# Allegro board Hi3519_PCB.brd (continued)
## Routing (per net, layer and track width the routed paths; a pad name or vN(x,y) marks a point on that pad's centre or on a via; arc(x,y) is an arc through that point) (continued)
SDIO1_CDATA1: length 66.9
  TOP w0.127: J12.8 R156.2 147.4,25.47 147.21,25.27 145.59,25.27 145.32,25.54 v2(144.05,25.54) ; v2(102.52,52.68) 102.18,52.34 R882.2
  ART03 w0.127: v2(144.05,25.54) 144.14,25.63 144.14,36.89 139.93,41.1 132.96,41.1 121.15,52.91 115.31,52.91 115,52.59 102.61,52.59 v2(102.52,52.68)
SDIO1_CDATA2: length 66.9
  TOP w0.127: J12.1 R157.2 147.4,33.75 147.1,34.05 144.73,34.05 143.21,35.57 v2(143.03,35.57) ; R880.2 v2(100.23,50.81)
  ART03 w0.127: v2(100.23,50.81) 100.23,50.33 100.44,50.13 101.68,50.13 101.9,50.35 101.9,51.43 102.3,51.83 114.97,51.83 115.22,51.58 120.49,51.58 131.85,40.21 134.34,40.21 134.49,40.06 134.49,39.7 134.64,39.55 134.85,39.55 135,39.7 135,40.19 135.15,40.34 135.36,40.34 135.51,40.19 135.51,39.7 135.66,39.55 135.87,39.55 136.02,39.7 136.02,40.19 136.17,40.34 136.38,40.34 136.53,40.19 136.53,39.7 136.67,39.55 136.88,39.55 137.03,39.7 137.03,40.19 137.18,40.34 137.39,40.34 137.54,40.19 137.54,39.7 137.69,39.55 137.9,39.55 138.05,39.7 138.05,40.19 138.2,40.34 138.41,40.34 138.56,40.19 138.56,39.7 138.71,39.55 138.93,39.55 139.08,39.7 139.08,40.19 139.23,40.34 139.44,40.34 139.59,40.19 139.59,39.7 139.74,39.55 140.4,39.55 143.03,36.92 v2(143.03,35.57)
SDIO1_CDATA3: length 64.4
  TOP w0.127: R788.2 v2(100.23,51.83) ; v2(143.67,34.1) 144.86,32.91 147.22,32.91 147.4,32.73 R154.2 J12.2
  ART03 w0.127: v2(143.67,34.1) 143.67,36.82 139.77,40.72 132.81,40.72 120.99,52.53 115.54,52.53 115.22,52.21 101.63,52.21 101.38,51.96 101.38,50.69 101.25,50.56 101,50.56 100.87,50.69 100.87,52.47 100.74,52.59 100.36,52.59 100.23,52.47 v2(100.23,51.83)
SDIO1_VOUT: length 80.7
  TOP w0.254: U3.M19 v1(93.7,50.79)
  TOP w0.381: R157.1 v2(145.93,33.48) ; R156.1 v2(145.9,25.78) ; v2(145.93,31.28) R153.1 R154.1 ; R155.1 v2(145.9,26.88)
  ART03 w0.381: v2(145.9,25.78) v2(145.9,26.88) 145.9,27.17 146.56,27.83 146.56,30.65 v2(145.93,31.28) 146.08,31.43 146.08,33.33 v2(145.93,33.48) 146.59,34.14 146.59,37.99 141.38,43.19 140.11,43.19 139.48,43.83 133.89,43.83 122.42,55.3 98.7,55.3 97.44,54.04 97.44,51.83 96.91,51.3 94.06,51.3 93.7,50.94 v1(93.7,50.79)
SELRGV: length 4.4
  TOP w0.127: R148.2 118.5,75.58 118.67,75.4 R1000.2 119,75.07 119.16,75.23 119.67,75.23 119.72,75.17 U2.14
SENSOR_CLK: length 39
  TOP w0.127: v2(53.75,39.64) 54.42,40.31 56.3,40.31 56.41,40.2 J1.12
  BOTTOM w0.127: v2(53.75,39.64) 53.75,37.45 56.01,35.19 71.66,35.19 77.24,40.78 81.92,40.78 82.83,41.7 R22.1
SENSOR_HS: length 42.8
  TOP w0.127: J1.18 54.15,41.4 v2(53.75,41.8)
  BOTTOM w0.127: v2(53.75,41.8) 53.24,41.29 53.24,37.42 55.85,34.81 71.81,34.81 77.4,40.4 82.1,40.4 R23.1
SENSOR_RSTN: length 42.3
  TOP w0.127: v1(83.3,44.94) 83.62,45.26 U3.Y4 ; J1.14 56.55,40.6 56.36,40.78 v2(53.75,40.78)
  BOTTOM w0.127: v1(83.3,44.94) 82.91,44.55 82.91,44.06 82.25,43.4 82.25,41.7 81.72,41.16 77.09,41.16 71.5,35.57 56.16,35.57 54.26,37.48 54.26,40.27 v2(53.75,40.78)
SENSOR_VS: length 37.7
  TOP w0.127: v2(54.89,42.43) 55.53,41.8 J1.20
  BOTTOM w0.127: v2(54.89,42.43) 54.74,42.28 54.74,37.54 56.32,35.96 71.34,35.96 76.93,41.54 81.44,41.54 81.69,41.8 R24.1
SGM8903_OUTL: length 5.8
  TOP w0.203: J30.1 9.58,32.17 10.03,32.62 D12.1 C215.1 R133.2
SGM8903_OUTR: length 9.6
  TOP w0.203: R134.1 C214.1 D11.1 6.87,29.62 6.43,30.06 J30.3
SHUTTER_TRIG: length 40.8
  TOP w0.127: U3.W14 v1(89.8,46.24) ; v2(123.73,38.75) 123.73,38.88 123.21,39.4 J18.60
  ART03 w0.127: v1(89.8,46.24) 89.8,47.11 90.07,47.39 91.85,47.39 92.36,46.88 92.36,46.24 92.86,45.73 98.86,45.73 99.79,44.81 101.37,44.81 102.25,43.92 116.61,43.92 121.27,39.26 123.22,39.26 v2(123.73,38.75)
SHUTTER_TRIG_C: length 55.7
  TOP w0.127: J17.5 J17.6 11.33,76.34 12.86,77.87 33.56,77.87 34.83,76.6 34.83,70.25 35.46,69.61 35.46,67.32 37.37,65.42 v2(37.37,64.91)
  BOTTOM w0.127: J19.60 41.18,54.6 37.67,58.1 37.67,63.46 37.37,63.77 v2(37.37,64.91)
SPI0_CSN: length 34.2
  TOP w0.127: J1.2 56.75,38.2 56.47,37.91 v2(56.47,37.18) ; v2(75.7,42.69) 82.35,42.69 U3.AB4
  BOTTOM w0.127: R135.1 v2(75.7,42.69) 75.34,42.33 75.34,41.04 71.02,36.72 56.93,36.72 v2(56.47,37.18)
SPI0_MISO: length 33.1
  TOP w0.127: v2(74.91,43.19) 82.2,43.19 U3.AB3 ; J1.4 56.67,38.6 55.93,37.86 v2(55.81,37.86)
  BOTTOM w0.127: v2(74.91,43.19) 74.91,41.14 70.87,37.1 57.69,37.1 56.93,37.86 v2(55.81,37.86)
SPI0_MOSI/I2C0_SDA: length 33.4
  TOP w0.127: v2(75.7,43.7) 80.8,43.7 80.93,43.58 81.94,43.58 U3.AB2 ; v2(56.17,38.75) 56.42,39 J1.6
  BOTTOM w0.127: v2(56.17,38.75) 56.67,38.75 57.94,37.48 70.71,37.48 74.44,41.21 74.44,43.51 74.63,43.7 v2(75.7,43.7) R51.1
SPI0_SCLK/I2C0_SCL: length 31.7
  TOP w0.127: v2(55.28,39.08) 55.52,39.33 56.34,39.33 56.41,39.4 J1.8
  BOTTOM w0.127: R500.1 R43.1 79.43,41.92 76.77,41.92 71.18,36.34 56.48,36.34 55.28,37.54 v2(55.28,39.08)
SVB_PWM_CPU: length 21.9
  TOP w0.127: U3.W16 91.1,45.59 v1(91.1,45.59)
  BOTTOM w0.127: v1(91.1,45.59) 91.1,44.33 91.52,43.91 93.12,43.91 93.38,44.16 98,44.16 98.71,43.45 101.76,43.45 102.68,42.52 109.34,42.52 109.63,42.81 R200.1
SVB_PWM_DDR: length 12
  TOP w0.127: v1(92.4,44.29) 92.4,44.94 U3.Y17
  BOTTOM w0.127: v1(92.4,44.29) 92.65,44.54 102.32,44.54 R202.2
SVB_PWM_MEDIA: length 28.5
  TOP w0.127: U3.Y16 91.1,44.94 91.1,38.2 v2(92.72,36.59)
  ART03 w0.127: v2(92.72,36.59) 93.58,35.73 107.32,35.73 108.82,34.23 v2(108.82,33.37)
  BOTTOM w0.127: R192.1 v2(108.82,33.37)
SVB_PWM_VDD: length 20.7
  TOP w0.127: U3.Y15 v1(90.45,45.59)
  ART03 w0.127: v2(91.34,28.72) 91.03,29.03 91.03,38.62 92.28,39.88 v1(92.28,40.68)
  BOTTOM w0.127: v1(90.45,45.59) 90.45,44.34 91.85,42.94 91.85,41.11 v1(92.28,40.68) ; R207.1 v2(91.34,28.72)
SYS_RSTN_OUT: length 45.5
  TOP w0.127: v2(76.87,30.24) 76.46,30.65 U16.3 ; v1(83.95,49.49) U3.P4 ; v2(88.73,30.62) U13.2
  ART03 w0.127: v2(76.87,30.24) 77.45,30.83 84.03,30.83 84.87,29.99 88.09,29.99 v2(88.73,30.62)
  ART04 w0.127: v1(83.95,49.49) 83.57,49.11 81.91,49.11 81.31,48.5 79.25,48.5 78.83,48.08 78.83,47.31 77.69,46.17 77.69,41 77.15,40.47 77.15,30.53 v2(76.87,30.24)
  BOTTOM w0.127: R213.2 77.75,28.97 76.87,29.86 v2(76.87,30.24) C212.2
TEST_MODE: length 3.9
  TOP w0.127: U3.R2 82,48.19 81.18,48.19 80.71,47.72 80.12,47.72 79.41,47.01 R93.1
TX0+_SII9022A: length 14.6
  TOP w0.102: J28.7 151.97,51.68 151.61,51.32 151.27,51.32 150.64,50.69 149.44,50.69 149.33,50.8 U12.10 U12.1 147.15,50.8 147.04,50.69 140.81,50.69 140.7,50.8 U22.62
TX0-_SII9022A: length 14.6
  TOP w0.102: J28.9 151.97,50.68 151.61,51.04 151.39,51.04 150.75,50.41 149.44,50.41 149.33,50.3 U12.9 U12.2 147.15,50.3 147.04,50.41 140.81,50.41 140.7,50.3 U22.61
TX1+_SII9022A: length 14.6
  TOP w0.102: J28.4 151.84,53.18 151.48,52.82 151.12,52.82 150.66,52.36 149.44,52.36 149.33,52.47 U11.7 U11.4 147.15,52.47 147.04,52.36 146.1,52.36 145.93,52.19 140.81,52.19 140.7,52.3 U22.65
TX1-_SII9022A: length 14.6
  TOP w0.102: U22.64 140.7,51.8 140.81,51.91 146.05,51.91 146.22,52.08 147.04,52.08 147.15,51.97 U11.5 U11.6 149.33,51.97 149.44,52.08 150.78,52.08 151.23,52.54 151.48,52.54 151.84,52.18 J28.6
TX2+_SII9022A: length 14.6
  TOP w0.102: U22.68 140.7,53.8 140.81,53.69 145.12,53.69 145.29,53.86 147.06,53.86 147.18,53.97 U11.1 U11.10 149.33,53.97 149.44,53.86 150.44,53.86 150.89,54.32 151.48,54.32 151.84,54.68 J28.1
TX2-_SII9022A: length 14.6
  TOP w0.102: J28.3 151.84,53.68 151.48,54.04 151.01,54.04 150.55,53.58 149.44,53.58 149.33,53.47 U11.9 U11.2 147.18,53.47 147.06,53.58 145.41,53.58 145.24,53.41 140.81,53.41 140.7,53.3 U22.67
TX_DSCL_SII9022A: length 20.1
  TOP w0.127: v2(137.45,45.48) 136.72,46.21 U22.49 ; v2(145.83,46.05) U17.1 147.28,46.05 147.99,46.75 150.49,46.75 151.41,47.68 J28.15
  ART03 w0.127: v2(145.83,46.05) 145.63,46.24 138.21,46.24 v2(137.45,45.48)
  BOTTOM w0.127: R183.1 v2(145.83,46.05)
TX_DSDA_SII9022A: length 20.9
  TOP w0.127: v2(148.05,46.05) U17.6 150.46,46.05 151.59,47.18 J28.16 ; U22.48 136.22,45.85 v2(136.59,45.48)
  ART03 w0.127: v2(148.05,46.05) 147.48,46.62 137.73,46.62 v2(136.59,45.48)
  BOTTOM w0.127: R184.1 v2(148.05,46.05)
TXC+_SII9022A: length 14.6
  TOP w0.102: U22.59 140.45,49.3 140.56,49.19 147.04,49.19 147.15,49.3 U12.4 U12.7 149.33,49.3 149.44,49.19 150.54,49.19 151.17,49.82 151.61,49.82 151.97,50.18 J28.10
TXC-_SII9022A: length 14.6
  TOP w0.102: J28.12 152.46,49.18 152.45,49.19 151.96,49.19 151.61,49.54 151.28,49.54 150.65,48.91 149.44,48.91 149.33,48.8 U12.6 U12.5 147.15,48.8 147.04,48.91 140.56,48.91 140.45,48.8 U22.58
TXDLY: length 6.6
  TOP w0.127: U2.16 119.7,74.37 119.65,74.31 119.27,74.31 119.23,74.35 117.1,74.35 116.89,74.56 R146.2 116.39,74.92 116.24,75.07 R1001.2
UART0_RXD: length 38.9
  TOP w0.127: U3.Y19 v1(93.7,44.94)
  ART03 w0.127: v1(93.7,44.94) 93.22,44.46 93.22,39.74 91.79,38.31 91.79,30.05 96.12,25.72 96.12,9.68 J25.3
UART0_TXD: length 38.8
  TOP w0.127: U3.Y18 v1(93.05,44.94)
  ART03 w0.127: J25.2 95.74,9.76 95.74,25.56 91.41,29.89 91.41,38.47 92.84,39.9 92.84,44.73 v1(93.05,44.94)
UART1_RTSN: length 33.9
  TOP w0.127: J18.58 123.3,40.2 v2(123.73,39.77) ; U3.V20 94.03,46.56 v1(94.35,46.24)
  ART03 w0.127: v2(123.73,39.77) 121.3,39.77 116.77,44.3 102.41,44.3 100.9,45.81 99.33,45.81 98.9,46.24 v1(94.35,46.24)
UART1_RTSN_C: length 21.7
  TOP w0.381: R230.1 R231.1 42.7,67.32 38.13,62.75 v2(36.99,62.75)
  BOTTOM w0.381: v2(36.99,62.75) 37.17,62.58 37.17,57.88 41.25,53.8 J19.58
UART1_RXD: length 35.6
  TOP w0.127: U3.U20 v1(94.35,46.89) ; J18.52 123.31,42.6 123.73,42.18 v2(123.73,40.78)
  ART03 w0.127: v2(123.73,40.78) 121.77,40.78 117.87,44.68 102.57,44.68 101.06,46.19 99.48,46.19 98.23,47.44 94.9,47.44 v1(94.35,46.89)
UART1_RXD_C: length 21.4
  TOP w0.127: v2(37.24,66.94) U6.1
  BOTTOM w0.127: v2(37.24,66.94) 35.49,65.19 35.49,56.24 36.98,54.75 38.01,54.75 41.36,51.4 J19.52
UART1_TXD: length 32.2
  TOP w0.127: J18.54 v2(121.44,41.8) ; U3.V19 v1(93.7,46.89)
  ART03 w0.127: v2(121.44,41.8) 118.18,45.06 102.73,45.06 101.22,46.57 99.64,46.57 98.39,47.82 94.63,47.82 v1(93.7,46.89)
UART1_TXD_C: length 23.5
  TOP w0.127: U6.4 41.05,67.58 40.04,66.56 v2(39.91,66.56)
  BOTTOM w0.127: J19.54 41.1,52.2 38.17,55.13 37.14,55.13 35.87,56.4 35.87,64.81 37.62,66.56 v2(39.91,66.56)
USB2_DM: length 30.5
  TOP w0.135: J18.17 117.37,56.2 117.13,55.95 116.92,55.95 115.47,57.4 115.47,59.5 114.61,60.37 105.67,60.37 104.83,59.53 104.83,57.4 102.38,54.96 100.59,54.96 100.44,55.11 100.44,55.36 100.29,55.51 100.08,55.51 99.93,55.36 99.93,55.11 99.77,54.96 97.94,54.96 97.34,54.35 95.34,54.35 U3.F22
USB2_DM_C: length 48.7
  TOP w0.135: v2(9.19,34.85) 9.46,35.13 9.46,35.23 D4.1 9.48,35.93 9.48,39.3 J14.2
  ART04 w0.114: v2(46.83,37.72) 46.62,37.93 45.82,37.93 45.52,37.63 45.52,34.95 44.49,33.92 9.68,33.92 9.35,34.25 9.35,34.69 v2(9.19,34.85)
  BOTTOM w0.135: J19.17 46.76,37.8 v2(46.83,37.72)
USB2_DP: length 30.5
  TOP w0.135: J18.19 117.37,55.4 117.13,55.64 116.79,55.64 115.16,57.27 115.16,59.37 114.48,60.05 105.8,60.05 105.14,59.4 105.14,57.27 102.51,54.64 98.07,54.64 97.47,54.04 95,54.04 U3.F21
USB2_DP_C: length 48.7
  TOP w0.135: v2(10.05,34.85) 9.78,35.13 9.78,35.23 D3.1 9.79,35.9 9.79,39.3 J14.3
  ART04 w0.114: v2(46.83,38.6) 46.83,38.33 46.71,38.21 45.71,38.21 45.24,37.75 45.24,35.07 44.38,34.2 9.8,34.2 9.63,34.37 9.63,34.67 9.81,34.85 v2(10.05,34.85)
  BOTTOM w0.135: J19.19 v2(46.83,38.6)
USB2_OVRCUR: length 42.5
  TOP w0.127: v1(91.75,44.94) 91.43,44.61 U3.AA16 ; v2(101.12,57.55) 101.12,60.09 102.42,61.38 114.84,61.38 117.62,58.6 J18.11
  BOTTOM w0.127: v2(101.12,57.55) 101.25,57.42 101.25,47.23 99.5,45.48 92.99,45.48 92.74,45.23 92.04,45.23 v1(91.75,44.94)
USB2_OVRCUR_C: length 32.9
  TOP w0.127: U1.3 23.27,46.23 23.14,46.1 23.14,44.21 v2(23.4,43.96)
  ART03 w0.127: v2(46.89,35.4) 46.31,34.81 42.45,34.81 34.96,42.31 30.26,42.31 28.61,43.96 v2(23.4,43.96)
  BOTTOM w0.127: J19.11 v2(46.89,35.4) ; v2(23.4,43.96) 22.89,44.46 R69.2
USB2_PWREN: length 30.3
  TOP w0.127: U3.F19 93.44,54.36 93.76,54.68 95.52,54.68 95.58,54.62 96.3,54.62 97.44,55.77 98.71,55.77 100.36,57.42 100.36,59.86 102.26,61.76 115,61.76 117.36,59.4 J18.9
USB2_PWREN_C: length 31.4
  TOP w0.127: v2(24.39,42.99) 25.46,44.06 R152.1 25.47,45.24 U1.4
  ART03 w0.127: v2(46.87,34.38) 46.82,34.43 42.29,34.43 34.8,41.92 30.1,41.92 28.45,43.58 24.97,43.58 v2(24.39,42.99)
  BOTTOM w0.127: v2(46.87,34.38) 46.65,34.6 J19.9
VDAC_CVBS: length 52.2
  TOP w0.127: J18.66 123.65,37 124.31,36.34 124.31,29.17 122.92,27.78 117.18,27.78 109.23,35.73 95.23,35.73 94.62,36.34 94.62,38.6 93.71,39.51 93.71,42.99 v1(93.91,43.19) 94.02,43.31 U3.AB20
  BOTTOM w0.127: R129.2 94.04,43.07 v1(93.91,43.19)
VDAC_CVBS_C: length 33.9
  TOP w0.127: v2(14,54.62) D2.1 J15.1
  ART04 w0.127: v2(40.93,56.78) 37.62,56.78 34.7,53.86 14.76,53.86 v2(14,54.62)
  BOTTOM w0.127: v2(40.93,56.78) 41.14,57 J19.66
VO_CLK: length 73.2
  TOP w0.127: U22.22 128.57,54.3 128.17,54.7 128.17,58.56 125.76,60.98 125.76,62.88 121.75,66.89 118.02,66.89 116.72,65.59 116.72,62.45 116.57,62.3 116.36,62.3 116.21,62.44 116.21,63.85 116.09,63.97 115.85,63.97 115.71,63.82 115.71,62.4 115.58,62.27 115.35,62.27 115.2,62.42 115.2,63.29 115.07,63.41 114.81,63.41 114.69,63.29 114.69,62.42 114.54,62.27 114.33,62.27 114.18,62.42 114.18,63.29 114.06,63.41 113.8,63.41 113.67,63.29 113.67,62.42 113.52,62.27 113.31,62.27 113.17,62.42 113.17,63.29 113.04,63.41 112.78,63.41 112.66,63.29 112.66,62.42 112.51,62.27 112.3,62.27 112.15,62.42 112.15,63.29 112.03,63.41 111.77,63.41 111.64,63.29 111.64,62.42 111.49,62.27 111.28,62.27 111.13,62.42 111.13,63.29 111.01,63.41 110.75,63.41 110.63,63.29 110.63,62.42 110.48,62.27 110.27,62.27 110.12,62.42 110.12,63.29 109.99,63.41 109.73,63.41 109.61,63.29 109.61,62.42 109.46,62.27 109.25,62.27 109.1,62.42 109.1,63.29 108.98,63.41 108.72,63.41 108.59,63.29 108.59,62.42 108.44,62.27 108.23,62.27 108.09,62.42 108.09,63.29 107.96,63.41 107.7,63.41 107.58,63.29 107.58,62.42 107.43,62.27 107.22,62.27 107.07,62.42 107.07,63.29 106.95,63.41 106.69,63.41 106.56,63.29 106.56,62.42 106.41,62.27 106.2,62.27 106.05,62.42 106.05,63.29 105.93,63.41 105.67,63.41 105.55,63.29 105.55,62.42 105.4,62.27 105.19,62.27 105.04,62.42 105.04,63.29 104.91,63.41 104.65,63.41 104.53,63.29 104.53,62.42 104.38,62.27 104.17,62.27 104.02,62.42 104.02,63.29 103.9,63.41 103.64,63.41 103.51,63.29 103.51,62.42 103.36,62.27 103.15,62.27 103.01,62.42 103.01,63.29 102.88,63.41 102.63,63.41 102.5,63.28 102.5,62.42 102.35,62.27 102.04,62.27 99.22,59.45 R700.1
VO_DATA0/BOOT_SEL0: length 80.5
  TOP w0.127: v2(99.85,58.05) 99.85,57.61 98.39,56.15 97.39,56.15 96.63,55.39 95.88,55.39 95.51,55.01 U3.E22 ; U22.13 v2(133.22,59.2) ; SW1.4 v2(98.81,76.46)
  ART03 w0.127: v2(99.85,58.05) 99.85,58.94 95.66,63.13 95.66,70.75 98.2,73.29 98.2,75.85 v2(98.81,76.46) 103.35,81 110.84,81 116.39,75.46 117.44,75.46 117.76,75.14 117.76,72.66 120.95,69.47 120.95,68.96 122.59,67.32 124.04,67.32 126.46,64.91 127.32,64.91 130.24,61.99 131.86,61.99 132.87,60.97 132.87,59.54 v2(133.22,59.2)
  BOTTOM w0.127: R60.2 v2(98.81,76.46)
VO_DATA1/BOOT_SEL1: length 82.4
  TOP w0.127: SW1.3 v2(97.56,76.46) ; U22.11 134.22,57.09 133.89,57.42 133.89,59.7 v2(133.38,60.21) ; U3.E21 95,55.34 95.5,55.34 95.78,55.63 96.46,55.63 97.36,56.53 98.23,56.53 98.96,57.26 v2(98.96,58.56)
  ART03 w0.127: v2(133.38,60.21) 133.38,61.01 132.01,62.37 130.4,62.37 127.48,65.29 126.62,65.29 123.44,68.47 121.98,68.47 121.33,69.12 121.33,69.72 118.14,72.91 118.14,75.29 117.59,75.84 116.55,75.84 111,81.38 102.48,81.38 v2(97.56,76.46) 96.93,75.83 96.93,72.91 95.28,71.26 95.28,61.86 98.58,58.56 v2(98.96,58.56)
  BOTTOM w0.127: R61.2 v2(97.56,76.46)
VO_DATA2/BOOTROM_SEL: length 87
  TOP w0.127: SW2.4 v2(91.82,76.46) ; v2(134.9,60.97) 134.27,60.34 134.27,57.8 134.72,57.35 U22.10 ; v2(97.57,57.04) 97.49,57.04 96.32,55.87 95.68,55.87 95.48,55.66 U3.D22
  ART03 w0.127: v2(134.9,60.97) 134.9,61.12 127.68,68.34 125.89,68.34 123.88,70.35 123.88,71.17 112.52,82.53 97.89,82.53 v2(91.82,76.46) 91.82,75.72 94.14,73.4 94.14,60.47 v2(97.57,57.04)
  BOTTOM w0.127: R67.2 v2(91.82,76.46)
VO_DATA3/SFC_EMMC_BOOT_MODE: length 84.9
  TOP w0.127: v2(135.41,60.09) 135.16,60.09 134.65,59.58 134.65,58.18 135.22,57.61 U22.9 ; U3.D21 95.01,56 95.47,56 95.58,56.11 96.18,56.11 97.06,56.99 97.06,57.29 97.69,57.93 v2(98.07,57.93) ; SW1.1 v2(95.06,76.46)
  ART03 w0.127: v2(98.07,57.93) 97.44,57.93 94.52,60.85 94.52,75.92 v2(95.06,76.46) 100.74,82.15 112.37,82.15 118.92,75.59 118.92,74.07 125.92,67.07 128.41,67.07 134.27,61.21 134.27,60.59 134.78,60.09 v2(135.41,60.09)
  BOTTOM w0.127: R63.2 v2(95.06,76.46)
VO_DATA4/SFC_DEVICE_MODE: length 80.1
  TOP w0.127: v2(135.16,59.07) 135.72,58.51 U22.8 ; U3.C22 95.36,56.35 96.02,56.35 96.68,57.01 96.68,57.93 v2(97.57,58.82) ; SW1.2 v2(96.31,76.46)
  ART03 w0.127: v2(97.57,58.82) 97.44,58.82 94.9,61.36 94.9,71.52 95.72,72.34 95.72,75.88 v2(96.31,76.46) 101.61,81.76 111.16,81.76 116.7,76.22 117.75,76.22 118.54,75.43 118.54,73.91 118.67,73.78 126.77,65.67 127.64,65.67 130.56,62.75 132.19,62.75 133.89,61.06 133.89,60.34 v2(135.16,59.07)
  BOTTOM w0.127: R62.2 v2(96.31,76.46)
VO_DATA5: length 73.6
  TOP w0.127: v1(96.3,57.16) 95.78,56.64 95,56.64 U3.C21 ; U22.7 v2(136.22,59.07)
  ART03 w0.127: v2(136.22,59.07) 134.91,57.76 130.81,57.76 130.43,57.38 108.88,57.38 108.63,57.63 108.63,60.65 108.48,60.8 108.27,60.8 108.13,60.65 108.13,57.53 107.98,57.38 107.77,57.38 107.62,57.53 107.62,60.65 107.47,60.8 107.26,60.8 107.11,60.65 107.11,57.77 106.82,57.48 105.43,57.48 105.08,57.83 105.08,65.01 104.81,65.29 101,65.29 100.51,64.81 100.51,57.24 99.8,56.53 96.93,56.53 v1(96.3,57.16)
VO_DATA6/UPDATE_FROM_SDIO0: length 86.7
  TOP w0.127: SW2.3 v2(90.57,76.46) ; U3.D20 v1(94.35,55.99) ; v2(136.68,60.09) 136.72,60.05 U22.6
  ART03 w0.127: v1(94.35,55.99) 94.3,55.99 93.76,56.53 93.76,73.02 90.57,76.21 v2(90.57,76.46) 97.02,82.91 112.68,82.91 126.87,68.72 127.84,68.72 136.48,60.09 v2(136.68,60.09)
  BOTTOM w0.127: R66.2 v2(90.57,76.46)
VO_DATA7: length 73.3
  TOP w0.127: U3.C20 v1(94.35,56.64) ; U22.4 137.72,57.12 137.29,57.55 v2(137.29,59.07)
  ART03 w0.127: v2(137.29,59.07) 135.6,57.38 130.97,57.38 129.96,56.37 118.95,56.37 118.81,56.5 118.81,56.85 118.66,57 118.45,57 118.3,56.85 118.3,56.04 118.15,55.89 117.94,55.89 117.8,56.04 117.8,56.85 117.65,57 117.44,57 117.29,56.85 117.29,56.04 117.14,55.89 116.93,55.89 116.78,56.04 116.78,56.85 116.63,57 116.42,57 116.27,56.85 116.27,56.04 116.12,55.89 115.91,55.89 115.76,56.04 115.76,56.85 115.61,57 115.4,57 115.26,56.85 115.26,56.04 115.11,55.89 114.9,55.89 114.75,56.04 114.75,56.85 114.6,57 114.39,57 114.24,56.85 114.24,56.04 114.09,55.89 113.88,55.89 113.73,56.04 113.73,56.85 113.58,57 113.37,57 113.22,56.85 113.22,56.04 113.07,55.89 112.86,55.89 112.72,56.04 112.72,56.85 112.57,57 112.36,57 112.21,56.85 112.21,56.56 112.02,56.37 104.96,56.37 104.42,56.9 104.42,63.41 104.15,63.69 102.11,63.69 101.66,63.24 101.66,56.66 101.15,56.15 95.77,56.15 95.28,56.64 v1(94.35,56.64)
VO_DATA8: length 73.5
  TOP w0.127: v2(127.03,58.94) 127.67,58.31 127.67,54.18 128.05,53.8 U22.23
  ART03 w0.127: v2(127.03,58.94) 127.03,59.65 126.73,59.96 122.6,59.96 122.41,60.15 122.41,61.66 122.26,61.81 121.76,61.81 121.61,61.66 121.61,61.12 121.46,60.97 121.25,60.97 121.1,61.12 121.1,61.66 120.96,61.81 120.75,61.81 120.6,61.66 120.6,61.12 120.45,60.97 120.24,60.97 120.09,61.12 120.09,61.66 119.94,61.81 119.73,61.81 119.58,61.66 119.58,60.74 119.43,60.59 119.22,60.59 119.07,60.74 119.07,61.66 118.92,61.81 118.71,61.81 118.56,61.66 118.56,60.74 118.42,60.59 118.21,60.59 118.06,60.74 118.06,61.66 117.91,61.81 117.67,61.81 117.52,61.66 117.52,60.74 117.37,60.59 117.16,60.59 117.01,60.74 117.01,61.66 116.86,61.81 116.65,61.81 116.5,61.66 116.5,60.74 116.36,60.59 116.15,60.59 116,60.74 116,61.66 115.85,61.81 115.64,61.81 115.49,61.66 115.49,60.74 115.34,60.59 115.13,60.59 114.98,60.74 114.98,61.66 114.83,61.81 114.62,61.81 114.47,61.66 114.47,60.74 114.32,60.59 114.11,60.59 113.96,60.74 113.96,61.66 113.82,61.81 113.61,61.81 113.46,61.66 113.46,60.74 113.31,60.59 112.96,60.59 112.81,60.74 112.81,67.3 112.66,67.45 112.45,67.45 112.3,67.3 112.3,60.74 112.15,60.59 111.94,60.59 111.79,60.74 111.79,67.32 111.66,67.45 111.41,67.45 111.28,67.32 111.28,63.64 111.16,63.51 110.9,63.51 110.77,63.64 110.77,68.78 v2(111.28,69.29)
  BOTTOM w0.127: v2(111.28,69.29) U10.46
VO_DATA9: length 53
  TOP w0.127: U22.20 129.02,55.3 128.68,55.64 128.68,58.82 v2(127.03,60.47)
  ART03 w0.127: v2(112.43,69.28) 113.19,68.52 113.19,62.35 113.34,62.19 113.55,62.19 113.7,62.34 113.7,64.89 113.84,65.04 114.05,65.04 114.2,64.89 114.2,62.34 114.35,62.19 114.56,62.19 114.71,62.34 114.71,64.89 114.86,65.04 115.07,65.04 115.22,64.89 115.22,62.34 115.37,62.19 122.64,62.19 122.79,62.05 122.79,60.49 122.94,60.34 123.15,60.34 123.3,60.49 123.3,62.05 123.45,62.19 123.66,62.19 123.81,62.05 123.81,60.49 123.95,60.34 124.16,60.34 124.31,60.49 124.31,62.05 124.46,62.19 124.67,62.19 124.82,62.05 124.82,60.49 124.97,60.34 125.18,60.34 125.33,60.49 125.33,62.05 125.48,62.19 125.69,62.19 125.84,62.05 125.84,60.72 126.09,60.47 v2(127.03,60.47)
  BOTTOM w0.127: v2(112.43,69.28) 111.91,69.79 U10.45
VO_DATA10: length 53.3
  TOP w0.127: U22.19 129.32,55.8 129.19,55.93 129.19,57.42 v2(129.82,58.05)
  ART03 w0.127: v2(110.85,71.79) 110.85,72.56 110.67,72.74 110.42,72.74 110.27,72.58 110.27,70.54 110.42,70.39 111.71,70.39 111.84,70.26 111.84,70.01 111.71,69.88 110.42,69.88 110.27,69.73 110.27,60.37 110.42,60.21 110.63,60.21 110.77,60.36 110.77,62.99 110.92,63.13 111.13,63.13 111.28,62.99 111.28,60.36 111.43,60.21 114.66,60.21 114.8,60.06 114.8,59.73 114.95,59.58 115.16,59.58 115.31,59.73 115.31,60.06 115.46,60.21 115.67,60.21 115.82,60.06 115.82,59.73 115.97,59.58 116.18,59.58 116.33,59.73 116.33,60.06 116.48,60.21 116.69,60.21 116.84,60.06 116.84,59.73 116.98,59.58 117.2,59.58 117.34,59.73 117.34,60.06 117.49,60.21 117.7,60.21 117.85,60.06 117.85,59.73 118,59.58 118.21,59.58 118.36,59.73 118.36,60.06 118.51,60.21 118.72,60.21 118.87,60.06 118.87,59.73 119.02,59.58 119.23,59.58 119.38,59.73 119.38,59.94 119.52,60.09 119.74,60.09 119.88,59.94 119.88,59.73 120.03,59.58 120.24,59.58 120.39,59.73 120.39,60.06 120.54,60.21 120.75,60.21 120.9,60.06 120.9,59.73 121.05,59.58 121.38,59.58 121.51,59.7 121.51,60.04 121.66,60.19 121.87,60.19 122.02,60.04 122.02,59.73 122.17,59.58 126.19,59.58 126.52,59.25 126.52,58.69 127.16,58.05 v2(129.82,58.05)
  BOTTOM w0.127: v2(110.85,71.79) U10.41
VO_DATA11: length 51.3
  TOP w0.127: v2(130.33,59.2) 130.72,58.81 U22.18
  ART03 w0.127: v2(130.33,59.2) 130.33,58.71 130.18,58.56 129.82,58.56 129.7,58.69 129.7,59.83 129.57,59.96 129.32,59.96 129.19,59.83 129.19,58.56 129.06,58.43 128.81,58.43 128.68,58.56 128.68,60.85 128.55,60.97 128.3,60.97 128.17,60.85 128.17,58.56 128.05,58.43 127.79,58.43 127.67,58.56 127.67,60.72 127.27,61.12 127.27,62.17 127.12,62.32 126.91,62.32 126.76,62.17 126.76,61.12 126.61,60.97 126.4,60.97 126.25,61.12 126.25,62.43 126.1,62.58 116.79,62.58 116.64,62.72 116.64,65.27 116.49,65.42 116.28,65.42 116.13,65.27 116.13,62.72 115.98,62.58 115.77,62.58 115.62,62.72 115.62,65.27 115.47,65.42 113.8,65.42 113.57,65.65 113.57,71.19 113.41,71.35 112.73,71.35 v2(111.79,72.29)
  BOTTOM w0.127: v2(111.79,72.29) U10.40
VO_DATA12: length 51.7
  TOP w0.127: U22.17 131.22,59.71 130.71,60.21 v2(130.33,60.21)
  ART03 w0.127: v2(130.33,60.21) 129.86,60.21 127.12,62.96 120.35,62.96 120.07,63.24 120.07,65.65 119.92,65.8 119.71,65.8 119.56,65.65 119.56,63.11 119.41,62.96 119.2,62.96 119.05,63.11 119.05,65.65 118.9,65.8 118.69,65.8 118.54,65.65 118.54,63.11 118.39,62.96 118.18,62.96 118.04,63.11 118.04,65.65 117.89,65.8 117.68,65.8 117.53,65.65 117.53,63.11 117.38,62.96 117.17,62.96 117.02,63.11 117.02,65.58 116.79,65.8 114.2,65.8 113.95,66.05 113.95,71.59 113.82,71.73 113.1,71.73 111.17,73.66 111.17,74.37 v2(110.75,74.79)
  BOTTOM w0.127: U10.35 v2(110.75,74.79)
VO_DATA13: length 52.2
  TOP w0.127: v2(131.72,59.2) U22.16
  ART03 w0.127: v2(110.77,75.71) 111.55,74.93 111.55,73.82 113.26,72.11 114.1,72.11 114.33,71.88 114.33,66.31 114.46,66.18 114.69,66.18 114.84,66.33 114.84,71.97 114.97,72.11 115.21,72.11 115.35,71.97 115.35,66.39 115.55,66.18 122.65,66.18 123.47,65.35 123.47,63.51 123.65,63.34 123.86,63.34 124,63.49 124,64.64 124.15,64.78 124.36,64.78 124.51,64.64 124.51,63.49 124.66,63.34 124.87,63.34 125.02,63.49 125.02,64.13 125.17,64.28 125.38,64.28 125.53,64.13 125.53,63.49 125.68,63.34 127.28,63.34 129.77,60.85 130.36,60.85 130.97,60.24 130.97,59.7 131.48,59.2 v2(131.72,59.2)
  BOTTOM w0.127: v2(110.77,75.71) 110.36,75.29 U10.34
VO_DATA14: length 48.4
  TOP w0.127: U22.15 132.22,59.47 v2(131.48,60.21)
  ART03 w0.127: v2(110.77,77.29) 111.24,77.29 112.01,76.52 112.01,75.41 113.85,73.57 113.85,72.71 114.07,72.49 115.48,72.49 115.73,72.25 115.73,66.69 115.85,66.56 116.11,66.56 116.24,66.69 116.24,71.24 116.37,71.37 116.6,71.37 116.74,71.23 116.74,66.72 116.9,66.56 117.1,66.56 117.25,66.71 117.25,67.68 117.4,67.83 117.61,67.83 117.76,67.68 117.76,66.71 117.91,66.56 123.73,66.56 126.14,64.15 127,64.15 129.92,61.23 130.52,61.23 131.48,60.27 v2(131.48,60.21)
  BOTTOM w0.127: v2(110.77,77.29) U10.30
VO_DATA15: length 49.5
  TOP w0.127: U22.14 132.72,59.86 v2(132.36,60.21)
  ART03 w0.127: v2(132.36,60.21) 131.89,60.68 131.61,60.68 130.68,61.61 130.08,61.61 127.16,64.53 126.3,64.53 123.89,66.94 120.34,66.94 120.19,67.09 120.19,69.64 120.05,69.79 119.82,69.79 119.68,69.65 119.68,67.09 119.53,66.94 119.32,66.94 119.17,67.09 119.17,68.32 119.03,68.47 118.82,68.47 118.67,68.32 118.67,67.09 118.52,66.94 118.31,66.94 118.16,67.09 118.16,70.2 118.01,70.35 117.78,70.35 117.65,70.22 117.65,68.36 117.5,68.21 117.29,68.21 117.14,68.36 117.14,71.37 115.64,72.87 114.5,72.87 114.23,73.14 114.23,73.72 112.39,75.57 112.39,76.68 110.82,78.25 110.53,78.25 v2(110.52,78.26)
  BOTTOM w0.127: U10.29 110.32,77.79 110.52,77.99 v2(110.52,78.26)
VO_DE: length 55.1
  TOP w0.127: U22.33 129.55,48.8 127.7,50.66 127.7,53.38 126.36,54.71 126.36,57.9 v2(126.4,57.93)
  ART03 w0.127: v2(126.4,57.93) 126.23,57.76 109.48,57.76 109.12,58.12 109.12,60.95 108.87,61.2 106.55,61.2 106.41,61.35 106.41,61.56 106.55,61.71 108.59,61.71 108.74,61.86 108.74,62.07 108.59,62.22 106.55,62.22 106.41,62.37 106.41,62.58 106.55,62.73 108.59,62.73 108.74,62.88 108.74,63.09 108.59,63.24 106.55,63.24 106.41,63.38 106.41,63.59 106.55,63.74 108.59,63.74 108.74,63.89 108.74,64.1 108.59,64.25 106.55,64.25 106.41,64.4 106.41,64.61 106.55,64.76 108.16,64.76 108.35,64.95 v2(108.35,65.79)
  BOTTOM w0.127: v2(108.35,65.79) U10.51
VO_HS: length 51
  TOP w0.127: v2(125.76,58.69) 125.86,58.59 125.86,54.68 127.31,53.22 127.31,50.5 129.51,48.3 U22.34
  ART03 w0.127: v2(109.89,79.01) 109.89,60.01 110.06,59.83 114.15,59.83 114.79,59.2 125.25,59.2 v2(125.76,58.69)
  BOTTOM w0.127: v2(109.89,79.01) 109.89,79.26 109.34,79.81 108.65,79.81 108.35,79.51 U10.26
VO_RGMII_SWITCH: length 20.1
  TOP w0.127: SW2.1 v2(88.07,76.47) 88.58,76.98 99.6,76.98 100.29,76.29 v2(101.76,76.29)
  BOTTOM w0.127: R64.2 v2(88.07,76.47) ; v2(101.76,76.29) U10.17
VO_VS: length 50.2
  TOP w0.127: U22.35 129.47,47.8 126.92,50.36 126.92,53.07 125.48,54.52 125.48,57.96 v2(124.74,58.69)
  ART03 w0.127: v2(124.74,58.69) 124.62,58.82 109.76,58.82 109.5,59.07 109.5,77.5 v2(107.85,79.16)
  BOTTOM w0.127: U10.25 v2(107.85,79.16)
$5N25: length 5.5
  TOP w0.356: C115.1 112.22,12.7 v2(112.22,13.35) U23.7
  BOTTOM w0.356: v2(112.22,13.35) 113.06,14.19 R73.1
$5N30: length 3.7
  TOP w0.356: U23.1 112.87,17.57 v2(113.32,18.02) 113.8,18.02 114.2,17.62 R81.1
  BOTTOM w0.356: v2(113.32,18.02) 113.06,17.76 R73.2
$5N37: length 2
  TOP w0.356: U23.6 111.57,13.6 v2(111.34,13.37)
  BOTTOM w0.356: R74.2 111.41,13.44 v2(111.34,13.37)
$5N45: length 1.6
  BOTTOM w0.356: C116.1 R248.2
$5N49: length 1.2
  BOTTOM w0.356: v2(111.36,18.48) 110.86,17.99 C116.2
$5N52: length 2.1
  TOP w0.356: U23.5 110.92,13.81 v2(110.47,13.37)
  BOTTOM w0.356: v2(110.47,13.37) 110.39,13.45 R248.1
$5N55: length 2
  TOP w0.356: U23.8 112.87,12.68 R100.1
$5N85: length 2.3
  TOP w0.356: U24.8 124.18,21.93 v2(123.98,21.73)
  BOTTOM w0.381: v2(123.98,21.73) 123.73,21.73 R99.1
$5N86: length 2.2
  TOP w0.356: U24.5 124.43,23.88 123.96,24.35 R247.1
$5N87: length 9.6
  TOP w0.381: C113.2 v2(120.93,23.76)
  ART04 w0.356: v2(129.19,24.78) 121.95,24.78 v2(120.93,23.76)
$5N88: length 1.3
  TOP w0.127: C113.1 R247.2
$5N91: length 2.1
  TOP w0.356: U24.6 124.22,23.23 v2(123.98,23.46)
  BOTTOM w0.381: v2(123.98,23.46) 124.06,23.38 R75.2
$5N94: length 4.8
  TOP w0.356: v2(127.08,21.22) 127.08,21.71 127.3,21.93 U24.1
  BOTTOM w0.381: v2(127.08,21.22) 126.75,20.89 R80.1 125.2,21.3 125.68,21.78 R72.2
$5N95: length 3.3
  TOP w0.356: v2(123.98,22.6) 124,22.58 U24.7
  TOP w0.381: C112.1 123.13,22.6 v2(123.98,22.6)
  BOTTOM w0.381: v2(123.98,22.6) 124.24,22.34 R72.1
$5N162: length 3.2
  TOP w0.356: R128.1 R41.2 112.81,10.94 113.06,11.19 R100.2
$5N171: length 3
  BOTTOM w0.381: R246.1 R103.2 R99.2
$6N20: length 2.8
  TOP w0.254: U9.1 62.4,70.38 v2(62.01,69.99)
  BOTTOM w0.381: R101.2 C13.1 v2(62.01,69.99)
$6N42: length 1.8
  BOTTOM w0.381: R187.2 R188.1
$6N44: length 1.8
  BOTTOM w0.381: R189.1 R253.2
$6N47: length 4.1
  BOTTOM w0.381: R188.2 R189.2 R193.1 R31.1
$6N77: length 4.1
  BOTTOM w0.356: U18.8 104.38,29.14 104.74,28.78 C119.1
  BOTTOM w0.381: C119.1 R82.2
$6N109: length 2.5
  BOTTOM w0.127: R192.2 C14.1 R190.1
$6N179: length 1.4
  BOTTOM w0.127: R190.2 R191.1
$6N194: length 1.7
  TOP w0.254: v2(63.02,69.99) 62.9,70.11 U9.2
  BOTTOM w0.381: R193.2 v2(63.02,69.99)
$6N199: length 2.4
  BOTTOM w0.356: U18.7 R194.1
$7N76: length 4
  TOP w0.381: v2(106.2,53.06) 106.99,52.28 C120.1 R83.2
  BOTTOM w0.356: v2(106.2,53.06) 106.46,52.81 U26.4
$7N92: length 9.5
  TOP w0.127: v2(114.08,50.59) 114.05,50.56 R198.1 113.31,50.56 R240.2 R11.1
  BOTTOM w0.127: R195.2 113.7,50.21 v2(114.08,50.59)
$7N111: length 2.7
  BOTTOM w0.127: R200.2 C15.1 R199.1
$7N113: length 1.4
  BOTTOM w0.381: R199.2 R195.1
$7N148: length 3.2
  BOTTOM w0.127: R201.2 C16.1 R202.1
$7N150: length 1.4
  BOTTOM w0.127: R196.2 R201.1
$7N160: length 4
  TOP w0.381: v2(106.2,51.35) 106.65,50.88 C121.1 107.92,50.88 108.3,50.5 R84.2
  BOTTOM w0.356: v2(106.2,51.35) 106.36,51.51 U26.2
$7N170: length 2.8
  TOP w0.381: v2(110.95,50.59) 110.98,50.56 R198.2
  BOTTOM w0.381: U26.8 110.68,50.86 v2(110.95,50.59)
$7N173: length 2
  BOTTOM w0.356: R197.1 106.63,50.56 106.93,50.86 U26.1
$7N232: length 4
  BOTTOM w0.127: R196.1 R12.1 R241.1 R197.2
$8N27: length 2.5
  BOTTOM w0.127: R206.1 C17.1 R207.2
$8N29: length 1.4
  BOTTOM w0.127: R205.1 R206.2
$8N42: length 3.5
  TOP w0.356: v2(94.9,19.01) 94.6,19.31 U27.4
  BOTTOM w0.381: v2(94.9,19.01) 94.96,19.08 C122.1 R85.2
$8N75: length 3.4
  TOP w0.356: U27.2 v2(93.3,19.01)
  BOTTOM w0.381: v2(93.3,19.01) C123.1 R86.2
$8N88: length 1.7
  TOP w0.356: U27.1 92.65,18.6 R203.1
$8N94: length 2.7
  TOP w0.356: v2(92.49,23.67) 92.65,23.5 U27.8
  BOTTOM w0.381: v2(92.49,23.67) 92.77,23.38 R204.2
$8N96: length 3.1
  TOP w0.356: R203.2 R245.2
  TOP w0.381: R245.2 R14.1
$8N120: length 2.3
  BOTTOM w0.127: C118.1 128.07,45.71 128.37,45.41 U21.4
$8N176: length 4
  BOTTOM w0.127: R204.1 R242.2 R13.1 R205.2
$10N57: length 2.4
  TOP w0.127: U3.K1 81.62,51.71 80.54,51.71 80.32,51.93 80.32,51.94 79.91,52.34 R113.2
$11N85: length 4.2
  TOP w0.203: 78.98,63.72 78.7,64 78.7,64.48 78.3,64.87 U14.L8
  TOP w0.381: 78.98,63.72 80.24,62.46 R114.2
$11N191: length 5.9
  TOP w0.203: U14.M8 77.11,64.72 77.11,63.64
  TOP w0.381: 77.11,63.64 77.11,63.22 76.18,62.3 C153.1 R175.2 R174.1
$11N192: length 4.9
  TOP w0.381: U14.H1 80.7,71.72 80.97,71.99 80.97,72.85 80.8,73.01 C156.1 R177.2 R176.1
$11N529: length 5.2
  BOTTOM w0.203: 79.28,71.39 79.02,71.39 78.7,71.06 78.7,70.55 78.3,70.16 U15.L8
  BOTTOM w0.381: 79.28,71.39 80.04,71.39 81.31,72.66 R115.2
$11N533: length 4.8
  BOTTOM w0.381: R179.1 R178.2 C161.1 80.24,63.86 U15.H1
$11N534: length 5.8
  BOTTOM w0.203: 77.9,71.13 77.9,70.32 U15.M8
  BOTTOM w0.381: 77.9,71.13 77.9,71.75 77.25,72.4 C159.1 R180.2 R181.1
$12N8: length 9.1
  TOP w0.127: X1.1 74.05,48.5 R29.2 74.78,48.43 C218.1 76.46,49.04 79.53,49.04 79.66,49.16 U3.P1
$12N11: length 5.2
  TOP w0.127: R249.2 75.77,50.41 C219.1 71.94,50.41 71.62,50.73 X1.3
$12N13: length 7.9
  TOP w0.127: U3.P2 82.01,49.48 81.18,49.48 81.12,49.42 75.95,49.42 R249.1 74.91,49.52 R29.1
$12N96: length 12.4
  TOP w0.127: X2.1 72.43,56.01 73.33,55.11 C2.1 74.1,55.11 74.71,54.5 74.71,54.12 78.24,50.59 80.73,50.59 80.93,50.39 81.6,50.39 U3.M1
$12N98: length 12.5
  TOP w0.127: X2.2 72.7,53.51 73.33,54.14 C3.1 74.15,54.14 78.08,50.21 80.68,50.21 80.74,50.15 82.01,50.15 U3.M2
$12N110: length 42.7
  TOP w0.127: U3.N3 82.65,49.49 82.65,49.04 82.45,48.84 80.1,48.84 79.33,48.07 v1(79.33,47.98)
  ART04 w0.127: v2(88.97,20.22) 86.72,22.47 82.89,22.47 79.02,26.33 79.02,30.41 77.88,31.55 77.88,40.65 78.07,40.85 78.07,46.01 79.33,47.27 v1(79.33,47.98)
  BOTTOM w0.127: U25.1 v2(88.97,20.22)
$12N181: length 3.3
  TOP w0.127: U3.A20 94.02,58.42 95.28,59.68 R19.2
$12N307: length 1.1
  TOP w0.127: U3.R3 v1(82.65,48.19)
  BOTTOM w0.127: R801.2 v1(82.65,48.19)
$12N323: length 6.7
  TOP w0.127: R8.2 95.79,59.76 94.35,58.32 94.35,57.47 94.16,57.28 93.83,57.28 93.59,57.04 93.45,57.04 U3.B19
$12N325: length 3.5
  TOP w0.127: U3.A21 94.67,58.13 96.3,59.76 R20.2
$12N327: length 6.8
  TOP w0.127: U3.B20 94.08,57.02 94.27,57.02 94.54,57.29 94.81,57.29 95,57.48 95,58 96.8,59.81 R25.2
$12N329: length 4.9
  TOP w0.127: R88.2 97.31,59.75 96.03,58.46 96.03,57.78 95.54,57.3 95.2,57.3 94.86,56.96 U3.B21
$12N331: length 2.5
  TOP w0.127: U3.C16 v1(91.75,56.64)
  BOTTOM w0.127: v1(91.75,56.64) 91.75,56.75 92.13,57.13 92.13,57.32 R90.2
$12N369: length 4.1
  TOP w0.127: U3.C17 v1(92.4,56.64)
  BOTTOM w0.127: v1(92.4,56.64) 92.4,56.82 R800.2
$12N378: length 3.4
  TOP w0.127: U3.D18 v1(92.35,55.29)
  BOTTOM w0.127: R21.2 93.25,56.4 93.25,56.19 v1(92.35,55.29)
$13N13: length 2
  TOP w0.127: U3.AA4 v1(83.3,44.29)
  BOTTOM w0.127: R22.2 82.83,43.37 83.3,43.84 v1(83.3,44.29)
$13N35: length 4
  TOP w0.127: U3.B22 95.55,56.96 96.27,57.68 96.27,58.17 97.55,59.45 R700.2
$13N216: length 2.5
  TOP w0.127: v1(83.95,44.94) 84.27,45.26 U3.Y5
  BOTTOM w0.127: v1(83.95,44.94) 83.85,44.84 R23.2
$13N220: length 4.5
  TOP w0.127: v1(83.95,45.59) 84.27,45.91 U3.W5
  BOTTOM w0.127: R24.2 81.69,43.42 82.45,44.19 82.45,44.85 83.2,45.59 v1(83.95,45.59)
$13N249: length 3.6
  TOP w0.127: v1(82,44.94) 82.65,44.94 U3.AA3
  BOTTOM w0.127: R500.2 80.68,43.25 81.49,44.06 81.49,44.43 v1(82,44.94)
$13N316: length 1.8
  TOP w0.127: SW1.5 R44.2
$13N317: length 1.8
  TOP w0.127: SW1.6 R46.2
$13N318: length 1.8
  TOP w0.127: SW1.7 R45.2
$13N319: length 1.8
  TOP w0.127: SW1.8 R42.2
$13N321: length 1.8
  TOP w0.127: R47.2 SW2.8
$13N322: length 1.8
  TOP w0.127: R48.2 SW2.7
$13N323: length 1.8
  TOP w0.127: SW2.6 R49.2
$13N324: length 1.8
  TOP w0.127: SW2.5 R50.2
$14N64: length 4.3
  TOP w0.127: v1(96.14,53.05) 95.97,53.05 95.63,53.39 94.35,53.39 U3.G20
  BOTTOM w0.127: R34.2 95.86,52.77 v1(96.14,53.05) 96.42,52.77 R33.2
$14N204: length 4.3
  TOP w0.254: C228.1 95.76,40.19 C47.1 94.67,42.51 U3.AB21
$14N216: length 5.6
  TOP w0.127: R26.1 98.35,48.27 98.11,48.51 U3.R22
$14N221: length 1.6
  TOP w0.127: U3.N21 v1(94.35,50.14)
  BOTTOM w0.127: v1(94.35,50.14) 94.65,50.43 R27.1
$14N244: length 5.4
  TOP w0.203: U3.Y22 95.73,45.26 96.17,44.82 96.65,44.82 97.29,44.18 97.29,43.09 98.46,41.92 C191.2
$14N249: length 6.9
  TOP w0.127: U3.Y21 95,44.93 95.52,44.93 95.8,44.66
  TOP w0.203: 95.8,44.66 96.02,44.44 96.58,44.44 96.86,44.16 96.86,42.76 98.01,41.61 98.01,41.23 98.33,40.91 C192.2
$14N260: length 3.6
  TOP w0.203: C194.2 97.8,45.99 97.74,46.04 97.73,46.04 97.21,46.56 97.21,46.56 U3.V22
$14N261: length 4.7
  TOP w0.127: 96.92,46.09 96.68,46.09 96.53,46.24 95,46.24 94.68,46.56 U3.V21
  TOP w0.203: C195.2 98.15,44.97 97.03,46.09 96.92,46.09
$14N269: length 7.9
  TOP w0.127: 94.28,42.7 94.28,42.98 94.35,43.05 94.35,44.1 94.02,44.43 U3.AA20
  TOP w0.254: 94.28,42.7 94.28,41.8 94.9,41.18 94.9,39.58 R91.1 R98.2
$14N610: length 5.7
  TOP w0.127: U3.N22 96.06,49.81 96.33,50.09 97.41,50.09 97.41,50.09 97.86,50.09 98.07,50.31 R780.1
$14N612: length 5
  TOP w0.127: U3.R20 94.36,48.17 95.59,48.17 95.63,48.13 97.96,48.13 98.32,47.77 R776.1
$14N614: length 5.8
  TOP w0.127: U3.T22 97.69,47.86 98.25,47.3 100.59,47.3 100.63,47.26 R778.1
$14N639: length 4.3
  TOP w0.127: R784.1 98.38,48.78 98.22,48.95 96.8,48.95 96.69,48.83 94.99,48.83 U3.R21
$14N641: length 5.6
  TOP w0.127: R782.1 98.42,49.29 98.38,49.33 96.55,49.33 96.39,49.16 U3.P22
$14N649: length 4.9
  TOP w0.127: U3.N20 94.34,49.49 96.25,49.49 96.46,49.71 97.41,49.71 97.41,49.71 98.51,49.71 98.6,49.71 R884.1
$14N651: length 6
  TOP w0.127: U3.L22 95.4,51.11 95.48,51.2 96.49,51.2 97.63,52.34 R882.1
$14N653: length 4.4
  TOP w0.127: U3.M21 95,50.14 95.88,50.14 96.13,50.4 97.33,50.4 97.41,50.47 97.7,50.47 98.04,50.81 R880.1
$14N655: length 4.6
  TOP w0.127: R788.1 97.69,51.83 96.78,50.92 95.69,50.92 95.56,50.79 95,50.79 U3.L21
$14N668: length 5.9
  TOP w0.127: U3.M22 95.82,50.46 96.03,50.68 97.17,50.68 97.82,51.32 R786.1
$14N704: length 1.4
  TOP w0.127: U3.P19 v1(93.05,48.84)
  BOTTOM w0.127: R92.1 93.65,49.44 v1(93.05,48.84)
$14N709: length 8.6
  TOP w0.127: R94.1 99.12,53.35 98.87,53.1 97.31,53.1 96.45,52.24 95.81,52.24 95.66,52.08 94.52,52.08 94.36,51.92 94.36,51.61 94.2,51.45 93.71,51.45 U3.L19
$15N123: length 3.9
  TOP w0.127: U7.19 R89.2 R136.1
$15N332: length 4.3
  TOP w0.127: v2(80.17,27.57) 80.07,27.47 U4.7
  BOTTOM w0.127: v2(80.17,27.57) 79.81,27.22 R212.1 R213.1
$16N153:
  vias: v2(128.17,76.72) v2(129.06,76.72)
$16N321: length 6.3
  TOP w0.508: T1.1 v2(134.14,76.5) ; T1.10 v2(134.14,67.5) ; T1.4 v2(134.14,73.5) ; T1.7 v2(134.14,70.5)
$16N389: length 26.9
  TOP w0.127: R4.2 v2(136.43,63.26)
  BOTTOM w0.127: v2(136.43,63.26) 144.77,63.26 148.49,66.98 148.49,69.69 149.75,70.95 J20.14
$16N404: length 1.7
  TOP w0.203: v2(126.85,71.82) 126.7,71.97 U2.39
  BOTTOM w0.254: R252.1 126.93,71.74 v2(126.85,71.82)
$16N414: length 2.4
  TOP w0.127: U2.42 126.41,73.17 126.66,73.42 R217.2 R216.2
$16N425: length 4.8
  TOP w0.203: C65.1 C239.1 128.94,68.04 128.81,67.92 LB11.2
$16N440: length 4.7
  TOP w0.203: OSC1.3 R28.1
$16N442: length 1.5
  TOP w0.203: R217.1 R28.2
$16N448: length 1.8
  TOP w0.203: R149.1 128.81,65.72
$16N468: length 6.2
  TOP w0.508: T1.18 v2(146.39,70.5) ; T1.21 v2(146.39,73.5) ; T1.24 v2(146.39,76.5) ; T1.15 v2(146.39,67.5)
$16N490: length 2.6
  TOP w0.203: U2.38 126.37,71.57 126.67,71.26 127.82,71.26 R218.2
$16N505: length 1.9
  TOP w0.127: R1004.2 118.74,72.4 119.51,73.17 U2.19
$16N560: length 7.8
  BOTTOM w0.127: J20.16 148.23,65.17 144.67,61.61 R5.2
$17N641: length 6.3
  TOP w0.127: R39.1 145.19,55.63 143.86,54.3 U22.69
$17N642: length 3.1
  TOP w0.127: U22.56 140.75,47.8 142.28,46.27 R214.1
$17N661: length 2.2
  TOP w0.127: R37.1 139.22,44.37 U22.54
$17N662: length 5.2
  TOP w0.127: U22.70 143.67,54.8 144.05,55.18 R35.1
$17N663: length 3.7
  TOP w0.127: U22.55 140.45,47.3 141.25,46.5 141.25,46.01 R38.1
$17N666: length 3.1
  TOP w0.127: R150.1 R151.1 141.44,55.8 U22.72
$17N672: length 3.8
  TOP w0.127: U22.51 137.72,45.99 138.08,45.63 138.08,44.38 C4.1 137.89,44.36 R36.2
$18N239: length 5.7
  TOP w0.127: R219.1 150.12,47.51 151.3,48.7 152.25,48.7 152.26,48.68 J28.13
$18N447: length 1.4
  TOP w0.127: D19.1 R6.2
$18N493: length 4
  BOTTOM w0.127: R184.2 R183.2 D20.1
$19N136: length 1.5
  TOP w0.127: U1.2 v2(22.89,46.88)
  BOTTOM w0.127: R112.1 v2(22.89,46.88)
$20N434: length 5.4
  TOP w0.127: R9.1 C179.2 R104.2 137.47,29.25 138.97,30.75
$20N436: length 1.7
  TOP w0.254: R54.2 Q3.1
$20N437: length 2.7
  TOP w0.127: R9.2 136.66,25.02 137.15,24.53 Q3.3
$20N553: length 4.4
  BOTTOM w0.127: Q2.1 C180.2 R105.2 R10.1
$20N554: length 1.7
  BOTTOM w0.127: R57.2 Q4.1
$20N555: length 2.5
  BOTTOM w0.127: R10.2 136.4,35.55 Q4.3
$21N200: length 4.2
  TOP w0.127: R235.1 v2(78.52,81.55)
  BOTTOM w0.127: R251.2 81.62,81.55 U19.7 v2(78.52,81.55)
$21N201: length 15
  TOP w0.127: v2(80.32,78.6) 77.63,78.6 76.84,79.39 R182.1 v2(75.98,80.28)
  BOTTOM w0.127: v2(80.32,78.6) R32.1 80.8,77.87 80.93,77.99 Q5.2 82.2,76.75 R1.1 ; v2(75.98,80.28) U19.1 73.69,80.28 72.7,79.29 R30.2 C181.2
$21N203: length 2.3
  BOTTOM w0.127: LB13.1 C221.1 R76.1
$21N204: length 4.2
  BOTTOM w0.127: R97.2 R250.2 R108.1 72.49,82.82 U19.3
$21N209: length 1.7
  BOTTOM w0.127: R1.2 84.23,76.49 Q5.1
$21N213: length 2.3
  BOTTOM w0.127: R97.1 C220.1 LB14.1
$21N216: length 2.9
  BOTTOM w0.127: U19.5 81.79,84.09 R109.1 R110.2
$21N217: length 2.7
  BOTTOM w0.127: 84.87,82.56 84.49,82.56 84.36,82.44 84.36,81.93 84.18,81.75 R78.1 R79.1
$21N220: length 2
  BOTTOM w0.127: R110.1 R40.1 R166.2
$21N227: length 3
  BOTTOM w0.127: 82.83,82.56 81.82,82.56 81.56,82.82 U19.6
$21N229: length 7.5
  TOP w0.127: R235.2 v2(75.98,81.55)
  BOTTOM w0.127: v2(75.98,81.55) U19.2 73.39,81.55 73.16,81.32 73.16,80.48 72.77,80.1 R30.1 C181.1 R76.2
$21N230: length 2.3
  BOTTOM w0.127: R111.1 C85.1 R2.2
$21N306: length 1.7
  TOP w0.127: U20.12 63.92,17.78 63.34,18.37 C124.2
$21N314: length 1.6
  TOP w0.127: U20.9 65.42,18.04 65.79,18.4 C87.1
$21N315: length 2
  TOP w0.127: U20.1 63.92,13.36 v2(63.91,13.35)
  BOTTOM w0.127: R243.1 v2(63.91,13.35)
$21N316: length 2
  TOP w0.127: v2(65.44,13.35) 65.42,13.36 U20.4
  BOTTOM w0.127: R244.1 v2(65.44,13.35)
$22N94: length 4.1
  TOP w0.203: J1.90 56.01,55.8 ; J1.84 56.01,54.6 ; J1.88 56.01,55.4 ; J1.86 56.01,55
  vias: v2(54.64,55.64) v2(54.64,54.62) v2(56.04,55.64) v2(56.04,54.62)
$24N1066: length 2.1
  TOP w0.127: R171.1 D15.2
$25N49: length 4
  TOP w0.203: R124.1 R125.2 v2(36.12,16.65)
  BOTTOM w0.203: v2(36.12,16.65) 36.5,16.27 C250.1
$25N63: length 3.9
  TOP w0.203: R126.1 40.67,15.76 v2(41.18,16.27) 41.18,17.06 R127.2
  BOTTOM w0.203: v2(41.18,16.27) C250.2
$25N107: length 2.8
  TOP w0.203: R117.2 C25.1 R116.1
$25N123: length 2.4
  TOP w0.203: R119.2 C26.1 R118.2
$25N140: length 5.2
  TOP w0.203: R120.1 R121.2 v2(32.92,16.91)
  BOTTOM w0.203: C249.1 31.91,17.92 v2(32.92,16.91)
$25N160: length 3.9
  TOP w0.203: R123.2 R122.1 v2(27.84,17.92)
  BOTTOM w0.203: v2(27.84,17.92) C249.2
$26N28: length 1.4
  TOP w0.203: C125.2 R131.1
$26N31: length 3.6
  TOP w0.203: R131.2 C144.1 R237.1 R16.1
$26N33: length 3.9
  TOP w0.356: C11.1 18.16,26.54 U5.2
  TOP w0.381: C11.1 18.04,26.02 17.18,25.16 R16.2
$26N37: length 9
  TOP w0.203: R134.2 R236.2 18.56,29.62 18.81,29.37 U5.3 18.81,26.46 C11.2 18.85,25.57 18.45,25.16 R237.2
$26N58: length 1.9
  TOP w0.127: U5.6 20.76,26.54 C7.2
$26N69: length 2.6
  TOP w0.127: v2(21.41,29.61) U5.7
  BOTTOM w0.127: C8.1 v2(21.41,29.61)
$26N71: length 2.5
  TOP w0.127: v2(21.41,32.78) U5.8
  BOTTOM w0.127: C8.2 v2(21.41,32.78)
$26N114: length 1.4
  TOP w0.203: R132.2 20.77,40.08 C126.1
$26N116: length 3.9
  TOP w0.203: R132.1 C143.1 R238.2 17.76,39.36 R17.2
$26N122: length 4.1
  TOP w0.203: U5.13 18.16,35.86 17.66,36.36 C12.2 17.66,37.4 R17.1
$26N127: length 8.7
  TOP w0.203: R133.1 R239.2 18.19,32.62 18.81,33.24 U5.12 18.81,36.38 C12.1 R238.1
$26N154: length 2.1
  TOP w0.127: R3.2 R15.2 R233.1
$26N162: length 2.6
  TOP w0.356: U5.11 19.46,36.56 R3.1
$27N23: length 2.5
  TOP w0.127: R172.2 24.5,61.65 24.12,61.26 U8.4
$27N24: length 2.2
  TOP w0.127: R173.2 24.44,63.57 24.12,63.89 U8.5
$27N30: length 1.4
  TOP w0.127: R172.1 C139.2
$27N32: length 1.2
  TOP w0.127: R173.1 C140.2
$27N58: length 3.8
  TOP w0.203: U8.1 22.17,62.15 22,62.32 21.46,62.32 LB18.1
$27N60: length 3.5
  TOP w0.203: LB19.1 21.38,62.78 21.95,62.78 22.17,63 U8.8
$27N64: length 5.5
  TOP w0.203: LB18.2 18.71,61.84 C210.1 17.02,62.24 15.07,62.24 J24.1
$27N67: length 5.6
  TOP w0.203: LB19.2 18.76,63.24 C211.1 16.92,62.72 15.25,62.72 J24.2
$28N945: length 10.1
  TOP w0.109: U6.6 39.78,72.69 39.67,72.58 39.39,72.58 39.28,72.47 39.28,72.16 38.49,71.37 36.85,71.37 36.22,72 36.22,75.95 R889.1
$28N947: length 4.1
  TOP w0.381: R231.2 40.29,69.97 39.78,69.46 U6.3
$28N948: length 7.6
  TOP w0.381: R230.2 43.44,70.75 39.78,70.75 38.51,69.48 U6.2
$28N1280: length 1.9
  TOP w0.127: Q6.1 R185.2
$28N1297: length 10.7
  TOP w0.127: K1.8 24.66,70.36 24.92,70.63 27.97,70.63 D16.1 33.18,69.99 Q6.3
$28N1347: length 9.2
  TOP w0.109: U6.7 38.51,72.69 38.62,72.58 38.9,72.58 39.01,72.47 39.01,72.27 38.38,71.64 36.96,71.64 36.49,72.12 36.49,75.95 R888.1

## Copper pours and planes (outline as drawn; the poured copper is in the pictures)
0.9V_VDD on TOP (solid shape): 103.15,26.18 103.15,24.53 102.9,24.27 95.79,24.27 95.66,24.4 95.66,26.2 95.8,26.34 102.99,26.34
0.9V_VDD on ART04 (solid shape): outline of 720 points within 84.38,24.27 103.15,51.7
0.9V_VDD on TOP: 88.09,48.4 87.91,48.58 87.91,50.56 88.04,50.69 89.01,50.69 89.08,50.61 89.08,48.48 89.01,48.4
0.9V_VDD_CPU on BOTTOM (solid shape): 91.58,53.47 91.58,52.61 91.65,52.54 91.65,51.88 91.57,51.81 90.48,51.81 90.4,51.88 90.4,52.21 91.47,52.21 91.47,52.47 91.22,52.47 91.22,52.21 90.96,52.21 90.96,52.47 90.71,52.47 90.71,52.21 90.4,52.21 90.4,52.44 90.28,52.57 89.69,52.57 89.59,52.67 89.59,52.87 89.69,52.97 91.34,52.97 91.34,53.1 91.09,53.1 91.09,52.97 89.69,52.97 89.77,53.05 89.77,53.1 90.45,53.1 90.45,53.35 90.33,53.35 90.33,53.1 89.77,53.1 89.77,53.43 89.91,53.57 91.48,53.57
0.9V_VDD_CPU on TOP: 90.1,52.24 89.34,53 89.34,53.23 89.4,53.29 91.03,53.29 91.32,53 91.32,52.52 91.04,52.24
0.9V_VDD_CPU on BOTTOM: 111.41,59.96 114.08,59.96 114.33,59.7 114.33,54.24 113.82,53.74 111.54,53.74 111.16,54.12 111.16,59.7
0.9V_VDD_CPU on ART04: 114.33,62.63 114.97,61.99 114.97,58.82 108.44,52.29 101.66,52.29 100.06,50.69 92.11,50.69 90.84,51.96 89.69,51.96 89.41,52.24 89.41,54.49 89.48,54.69 89.41,54.89 89.41,55.14 89.48,55.34 89.41,55.54 89.41,55.79 89.48,55.99 89.41,56.19 89.41,56.44 89.48,56.59 89.46,56.75 89.45,56.79 95.28,62.63 98.68,62.63 98.77,62.59 98.81,62.5 99.22,62.09 99.62,62.5 99.66,62.59 99.75,62.63
0.9V_VDD_DDR on BOTTOM: 105.28,53.74 102.65,53.74 102.14,54.25 102.14,59.7 102.39,59.96 105.19,59.96 105.42,59.72 105.42,53.88
0.9V_VDD_DDR on POWER5: 92.29,50.56 90.89,51.96 86.57,51.96 86.26,52.26 86.26,53.68 86.32,53.74 89.11,53.74 89.49,54.12 94.95,54.12 95.08,54.24 95.26,54.24 97.04,56.02 100.74,56.02 101.76,57.04 101.76,59.58 102.01,59.83 104.55,59.83 105.06,59.32 105.06,51.32 104.42,50.69 96.95,50.69 96.83,50.56
0.9V_VDD_MEDIA on BOTTOM (solid shape): 105.44,34.18 105.44,31.71 104.6,30.88 103.18,30.88 103.13,30.93 103.13,31.79 102.9,32.02 99.7,32.02 99.04,32.68 97.19,32.68 97.06,32.81 97.06,34.05 97.44,34.43 105.19,34.43
0.9V_VDD_MEDIA on BOTTOM (solid shape): 87.41,48.22 87.41,47.33 87.28,47.2 86.66,47.2 86.63,47.21 86.58,47.22 86.52,47.22 86.47,47.21 86.44,47.2 86.39,47.2 86.26,47.07 86.26,47.06 86.25,47.02 86.23,46.98 86.22,46.93 86.22,46.88 86.22,46.83 86.22,46.78 86.24,46.72 86.11,46.59 85.73,46.59 85.63,46.69 85.63,47.51 86.9,47.51 86.9,47.89 86.64,47.89 86.64,47.51 86.39,47.51 86.39,47.89 86.14,47.89 86.14,47.51 85.63,47.51 85.63,48.22 85.76,48.34 87.28,48.34
0.9V_VDD_MEDIA on BOTTOM (solid shape): 91.32,50.31 91.32,49.04 91.08,48.8 91.08,47.75 90.96,47.64 89.69,47.64 89.57,47.77 89.57,48.15 90.84,48.15 90.84,48.4 90.45,48.4 90.45,48.15 89.95,48.15 89.95,48.4 89.69,48.4 89.69,48.15 89.57,48.15 89.57,48.78 90.84,48.78 90.84,49.04 90.58,49.04 90.58,48.78 89.57,48.78 89.57,48.91 89.69,49.04 90.07,49.04 90.25,49.21 90.25,49.62 90.33,49.7 90.68,49.7 90.78,49.8 90.78,50.31 90.89,50.41 91.22,50.41
0.9V_VDD_MEDIA on ART04: 88.88,48.27 89.76,49.16 89.82,49.16 89.86,49.16 90,49.16 90.2,49.37 90.2,49.6 90.78,50.18 98.35,50.18 98.71,49.82 98.71,39.77 99.37,39.11 103.46,39.11 105.44,37.12 105.44,32.91 105.19,32.65 91.85,32.65 86.9,37.61 86.9,45.68 86.84,45.74 86.81,45.79 86.78,45.82 86.74,45.91 86.78,46 86.83,46.41 86.45,46.56 86.34,46.58 86.29,46.68 86.29,48.35 86.34,48.4 86.44,48.4 87.38,48.4 87.52,48.26 87.52,48.23 87.81,47.86 88.18,48.16 88.22,48.24 88.3,48.27
1.2V_SII9022 on BOTTOM: 130.59,48.4 130.97,48.02 138.92,48.02 138.97,47.97 138.97,46.6 138.87,46.5 132.62,46.5 132.36,46.24 132.36,44.46 131.97,44.07 130.07,44.07 129.95,44.19 129.95,45.35 129.93,45.38 129.65,45.38 129.62,45.35 129.62,44.13 129.57,44.08 129.06,44.08 128.94,44.21 128.94,49.93 129.06,50.05 130.46,50.05 130.59,49.93 ; 6 cut-outs
1.8V on TOP (solid shape): 101.4,18.25 101.4,16.19 101.2,15.99 95.81,15.99 95.66,16.14 95.66,18.3 95.79,18.43 101.22,18.43
1.8V on BOTTOM: 78.69,42.18 78.62,42.26 77.93,42.26 77.88,42.31 77.88,44.46 78.01,44.59 80.9,44.59 81.03,44.46 81.03,44.08 80.19,43.25 80.19,42.76 80.14,42.71 79.3,42.71 79.15,42.56 79.15,42.31 79.02,42.18 ; 6 cut-outs
1.8V on ART03: 85.25,47.77 88.3,47.77 88.55,47.51 88.55,46.63 88.53,46.59 88.49,46.57 88.37,46.54 88.26,46.47 88.17,46.44 88.08,46.47 87.64,46.5 87.57,46.06 87.58,45.93 87.47,45.86 86.74,45.86 86.72,45.87 86.55,45.92 86.38,45.87 86.36,45.86 86.28,45.86 86.17,45.93 86.17,46.06 85.9,46.57 85.62,46.06 85.63,45.93 85.52,45.86 84.79,45.86 84.77,45.87 84.56,45.92 84.36,45.82 84.27,45.78 84.18,45.82 83.71,45.82 83.72,45.36 83.75,45.27 83.62,45.14 83.53,45.17 83.06,45.17 83.07,44.71 83.1,44.61 83.07,44.52 82.98,44.38 82.98,44.21 82.97,44.2 82.97,43.84 82.71,43.58 80.68,43.58 80.29,43.96 80.29,46.12 81.31,47.13 84.61,47.13
1V2A_SII9022A on BOTTOM (solid shape): 141.38,52.95 141.38,52.21 141.13,51.96 140.62,51.96 140.49,51.83 140.49,50.81 140.62,50.69 141.13,50.69 141.38,50.43 141.38,49.42 140.87,48.91 140.87,48.44 140.87,48.43 140.85,48.3 140.87,48.17 140.87,48.16 140.87,46.93 140.72,46.78 139.76,46.78 139.6,46.93 139.6,49.85 140.34,49.85 140.34,50.76 139.6,50.76 139.6,52.34 140.34,52.34 140.34,53.13 141.2,53.13
1V2D_SII9022A on BOTTOM (solid shape): outline of 217 points within 128.55,44.03 144.05,56.28
3V3 on TOP (solid shape): 65.31,20.33 65.31,18.3 65.05,18.05 64.29,18.05 64.04,18.3 64.04,20.33 64.29,20.59 65.05,20.59
3V3 on TOP (solid shape): 95.66,34.05 95.66,31.38 95.53,31.26 94.14,31.26 94.01,31.38 94.01,34.05 94.26,34.3 95.41,34.3
